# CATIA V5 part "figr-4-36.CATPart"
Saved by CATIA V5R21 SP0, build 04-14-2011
Part number: Part1
Bounding box of the stored display mesh (mm): x 0 to 127.525, y -106.271 to 100, z 0 to 100
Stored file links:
  D:\CATIA V5R21 E-RESOURCES\CATIA-V5R21\catia-v5r21-prt\c04-catia-v5r20-prt\catia-v5r21-figr-4-36.CATPart
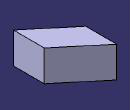
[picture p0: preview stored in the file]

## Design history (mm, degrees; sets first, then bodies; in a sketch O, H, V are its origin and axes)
Body1 (main body)
  Sketch1 on yz-plane, origin (0, 0, 0), H (0, 1, 0), V (0, 0, 1)
    line L1 (0, 0) -> (100, 0)
    line L2 (100, 0) -> (100, 100)
    line L3 (100, 100) -> (0, 100)
    line L4 (0, 100) -> (0, 0)
    horizontal: L1 H, L3 H
    vertical: L2 V, L4 V
  Sketch2 on xy-plane, origin (0, 0, 0), H (1, 0, 0), V (0, 1, 0)
    line L1 (0, 0) -> (60, -50)
  Pad1: profile Sketch1, direction along edge of Sketch2, length 166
